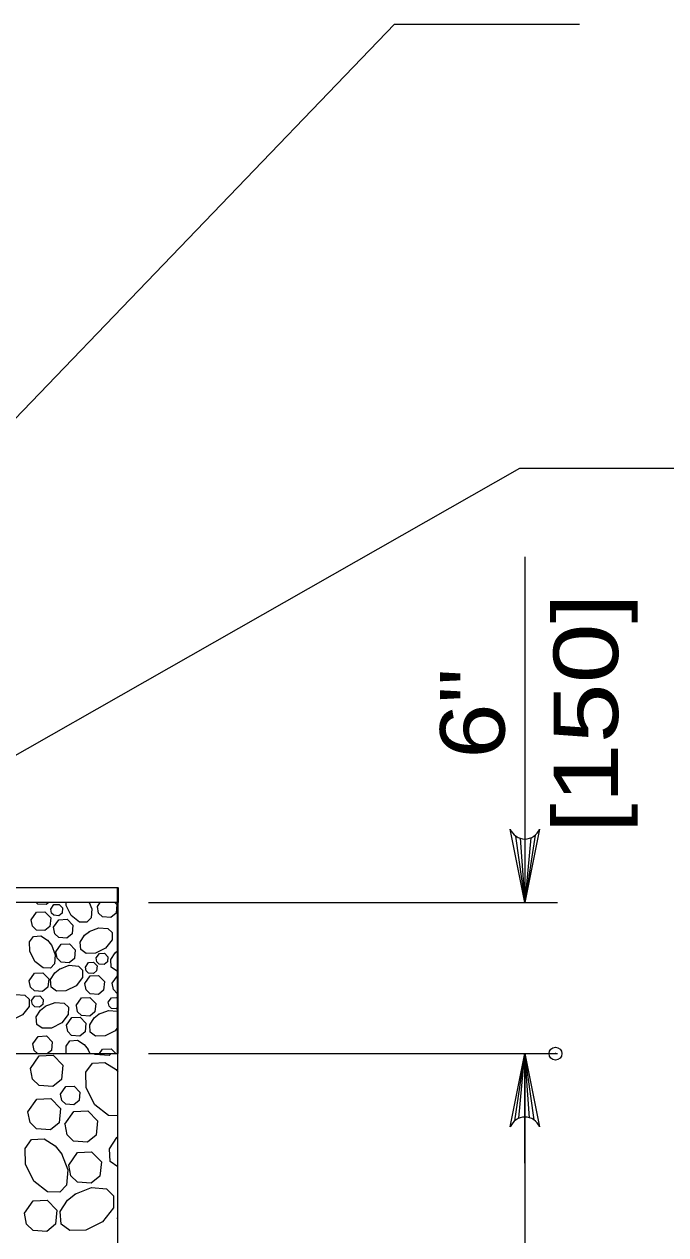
# Model space of a CAD drawing. Extents: x 1083.1 to 1117.1, y 697.4 to 741.4.
# Drawn here: x 1100.973 to 1102.523, y 705.8 to 708.723 of the extents above; entities that cross this region are included whole.
import ezdxf
from ezdxf.enums import TextEntityAlignment as Align

# ---------------------------------------------------------------- set-up
doc = ezdxf.new("R2010")
doc.units = 0
doc.header["$LTSCALE"] = 0.062
doc.header["$PDMODE"] = 32
doc.header["$PDSIZE"] = 0.031
doc.layers.add('1', color=7, linetype='Continuous', lineweight=13)

msp = doc.modelspace()

# ---------------------------------------------------------------- linework, layer by layer
at = {"layer": '1'}
for p, q in [((1102.18242, 707.4375), (1102.18242, 706.60292)), ((1102.16, 706.76317), (1102.18242, 706.60292)), ((1102.17108, 706.75767), (1102.18242, 706.60292)), ((1102.20725, 706.765), (1102.18242, 706.60292)), ((1102.19683, 706.75892), (1102.18242, 706.60292)), ((1102.18242, 706.75608), (1102.18242, 706.60292)), ((1101.14967, 706.593), (1101.15667, 706.60292)), ((1101.27317, 706.60292), (1102.26108, 706.60292)), ((1101.12683, 706.24842), (1101.13108, 706.23775)), ((1101.27317, 706.23775), (1102.26108, 706.23775)), ((1102.15767, 706.07558), (1102.18242, 706.23775)), ((1102.16808, 706.08175), (1102.18242, 706.23775)), ((1102.18242, 706.23775), (1102.18242, 704.29175)), ((1102.18242, 705.97342), (1102.18242, 706.23775)), ((1102.18242, 706.08458), (1102.18242, 706.23775)), ((1102.19375, 706.08292), (1102.18242, 706.23775)), ((1102.20483, 706.0775), (1102.18242, 706.23775)), ((1101.19808, 705.841), (1101.19942, 705.84283)), ((1101.19942, 705.8345), (1101.19808, 705.84092))]:
    msp.add_line(p, q, dxfattribs=at)
at = {"layer": '1', "lineweight": 25}
for p, q in [((1101.19942, 706.63767), (1098.91383, 706.63767)), ((1098.91383, 706.23775), (1101.19942, 706.23775))]:
    msp.add_line(p, q, dxfattribs=at)
at = {"layer": '1'}
for points in [[(1099.87325, 706.64992), (1101.86758, 708.7235), (1102.3145, 708.7235)], [(1100.01742, 706.42642), (1102.17033, 707.65183), (1102.60283, 707.65183)], [(1102.21783, 706.77992), (1102.18242, 706.60292), (1102.14708, 706.77992)], [(1101.03267, 706.60292), (1101.02608, 706.59742), (1101.00608, 706.59883), (1101.00183, 706.60292)], [(1101.13008, 706.60292), (1101.13625, 706.58717), (1101.13442, 706.56533), (1101.1245, 706.555), (1101.10675, 706.55525), (1101.08675, 706.571), (1101.0745, 706.59533), (1101.07442, 706.60292)], [(1101.19158, 706.60292), (1101.19675, 706.5975), (1101.19467, 706.57708), (1101.18217, 706.56667), (1101.16208, 706.56808), (1101.15275, 706.57725), (1101.14967, 706.593)], [(1101.0385, 706.50033), (1101.04792, 706.47658), (1101.04608, 706.45475), (1101.03625, 706.44433), (1101.0185, 706.44475), (1100.99842, 706.4605), (1100.98625, 706.48483), (1100.98592, 706.50767), (1100.995, 706.52058), (1101.01325, 706.52183), (1101.02958, 706.51133), (1101.03917, 706.49933)], [(1101.12967, 706.53242), (1101.15333, 706.54183), (1101.17525, 706.53992), (1101.1855, 706.53008), (1101.18525, 706.51242), (1101.1695, 706.49225), (1101.14517, 706.48017), (1101.12225, 706.47967), (1101.10942, 706.48892), (1101.10817, 706.50717), (1101.11858, 706.52342), (1101.13067, 706.533)], [(1101.19942, 706.43733), (1101.19592, 706.43725), (1101.183, 706.4465), (1101.18183, 706.46475), (1101.19233, 706.481), (1101.19942, 706.48667)], [(1101.05817, 706.44158), (1101.08192, 706.45108), (1101.10375, 706.44917), (1101.11408, 706.43933), (1101.11375, 706.42167), (1101.09808, 706.4015), (1101.07375, 706.38933), (1101.05083, 706.38892), (1101.03792, 706.39808), (1101.03667, 706.41633), (1101.04717, 706.43267), (1101.05917, 706.44225)], [(1101.18517, 706.40783), (1101.19792, 706.42592), (1101.19942, 706.426)], [(1101.19942, 706.38283), (1101.19767, 706.383), (1101.18825, 706.39217), (1101.18525, 706.40783)], [(1100.92908, 706.37142), (1100.95283, 706.38083), (1100.97467, 706.37892), (1100.985, 706.36908), (1100.98467, 706.35142), (1100.969, 706.33125), (1100.94467, 706.31917), (1100.92167, 706.31875), (1100.90875, 706.32783), (1100.90758, 706.34608), (1100.91808, 706.3625), (1100.93, 706.372)], [(1100.99075, 706.36583), (1100.99842, 706.37667), (1101.01058, 706.37733), (1101.019, 706.36858), (1101.01783, 706.35633), (1101.01025, 706.35008), (1100.99833, 706.35092), (1100.99267, 706.35642), (1100.99083, 706.36583)], [(1101.02375, 706.35192), (1101.04742, 706.36133), (1101.06925, 706.3595), (1101.07958, 706.34958), (1101.07925, 706.33192), (1101.0635, 706.31183), (1101.03925, 706.29958), (1101.01633, 706.29925), (1101.00342, 706.30833), (1101.00217, 706.32658), (1101.01267, 706.343), (1101.02467, 706.35258)], [(1101.09883, 706.35425), (1101.11158, 706.37233), (1101.13183, 706.3735), (1101.146, 706.35883), (1101.14392, 706.33842), (1101.13133, 706.32792), (1101.11133, 706.32942), (1101.10192, 706.33858), (1101.09892, 706.35425)], [(1101.17583, 706.36167), (1101.1835, 706.3725), (1101.19567, 706.37317), (1101.19942, 706.36933)], [(1101.19942, 706.34925), (1101.19533, 706.34592), (1101.18342, 706.34675), (1101.17775, 706.35225), (1101.17592, 706.36167)], [(1101.19942, 706.30133), (1101.1925, 706.29267), (1101.16825, 706.28042), (1101.14533, 706.28), (1101.13242, 706.28917), (1101.13117, 706.30742), (1101.14167, 706.32375), (1101.15367, 706.33342)], [(1101.15267, 706.33275), (1101.17642, 706.34208), (1101.19817, 706.34025), (1101.19942, 706.33908)], [(1100.99358, 706.26117), (1101.00633, 706.27925), (1101.02658, 706.28033), (1101.04067, 706.26583), (1101.03858, 706.24533), (1101.0295, 706.23775)], [(1101.00467, 706.23775), (1100.99667, 706.2455), (1100.99358, 706.26117)], [(1101.07442, 706.23775), (1101.07417, 706.25583), (1101.08333, 706.26875), (1101.10158, 706.26992), (1101.11792, 706.25942), (1101.1275, 706.2475)], [(1100.98792, 706.20183), (1101.00908, 706.232), (1101.04292, 706.23383), (1101.06633, 706.20958), (1101.063, 706.17542), (1101.04217, 706.15808), (1101.00875, 706.1605), (1100.993, 706.17575), (1100.988, 706.20183)], [(1101.18275, 706.23775), (1101.17775, 706.23358), (1101.14442, 706.236), (1101.14258, 706.23775)], [(1101.15475, 706.23775), (1101.16233, 706.2485), (1101.18258, 706.24967), (1101.19408, 706.23775)], [(1102.14708, 706.06075), (1102.18242, 706.23775), (1102.21783, 706.06075)], [(1101.19942, 706.08758), (1101.17667, 706.08792), (1101.14317, 706.11425), (1101.12283, 706.15475), (1101.12217, 706.19292), (1101.1375, 706.21442), (1101.16792, 706.21642), (1101.19517, 706.199), (1101.19942, 706.19367)], [(1101.06058, 706.14017), (1101.07333, 706.15825), (1101.09358, 706.15942), (1101.10767, 706.14483), (1101.10567, 706.12433), (1101.09308, 706.11392), (1101.07308, 706.11542), (1101.06367, 706.1245), (1101.06067, 706.14017)], [(1101.07142, 706.0675), (1101.09258, 706.09758), (1101.12633, 706.0995), (1101.14983, 706.07517), (1101.14642, 706.04108), (1101.12558, 706.02367), (1101.09225, 706.02608), (1101.0765, 706.04133), (1101.0715, 706.0675)], [(1101.06283, 705.99633), (1101.07858, 705.95683), (1101.07542, 705.92042), (1101.059, 705.90317), (1101.0295, 705.90367), (1100.99592, 705.92992), (1100.97575, 705.97042), (1100.975, 706.00867), (1100.99025, 706.03008), (1101.02075, 706.03217), (1101.04792, 706.01467), (1101.06383, 705.99475)], [(1101.19942, 705.96408), (1101.18092, 705.97725), (1101.17883, 706.00767), (1101.19633, 706.03492), (1101.19942, 706.03733)], [(1101.09558, 705.8985), (1101.13517, 705.91425), (1101.1715, 705.91108), (1101.18883, 705.89467), (1101.18825, 705.86517), (1101.162, 705.83167), (1101.1215, 705.81133), (1101.08333, 705.81075), (1101.06183, 705.826), (1101.05983, 705.85642), (1101.07717, 705.88358), (1101.09717, 705.8995)], [(1100.97358, 705.85208), (1100.99475, 705.88225), (1101.02858, 705.88408), (1101.052, 705.85983), (1101.04867, 705.82567), (1101.02783, 705.80833), (1100.99442, 705.81075), (1100.97875, 705.826), (1100.97367, 705.85208)]]:
    msp.add_lwpolyline(points, dxfattribs=at)
at = {"layer": '1', "lineweight": 25}
for points in [[(1101.19942, 706.23775), (1101.19942, 706.63767), (1101.19942, 706.60292), (1098.91383, 706.60292)], [(1100.04408, 704.29175), (1101.19942, 704.29175), (1101.19942, 706.63767)], [(1101.19942, 706.23775), (1101.19942, 706.63767), (1101.19942, 706.60292)]]:
    msp.add_lwpolyline(points, dxfattribs=at)
at = {"layer": '1', "lineweight": 35}
msp.add_lwpolyline([(1101.19942, 706.23775), (1101.19942, 706.63767), (1101.19942, 706.60292)], dxfattribs=at)
at = {"layer": '1'}
for points in [[(1100.99008, 706.561), (1101.00275, 706.579), (1101.023, 706.58017), (1101.03708, 706.56558), (1101.03508, 706.54508), (1101.0225, 706.53467), (1101.00258, 706.53608), (1100.99308, 706.54525)], [(1101.03725, 706.58667), (1101.04483, 706.5975), (1101.057, 706.59817), (1101.06542, 706.58942), (1101.06425, 706.57717), (1101.05667, 706.57083), (1101.04475, 706.57175), (1101.03908, 706.57725)], [(1101.04367, 706.543), (1101.05633, 706.56108), (1101.07667, 706.56225), (1101.09075, 706.54767), (1101.08867, 706.52717), (1101.07617, 706.51675), (1101.05617, 706.51817), (1101.04675, 706.52733)], [(1101.04933, 706.48367), (1101.062, 706.50167), (1101.08233, 706.50283), (1101.09642, 706.48817), (1101.09433, 706.46775), (1101.08183, 706.45733), (1101.06183, 706.45875), (1101.05242, 706.46792)], [(1101.14675, 706.46883), (1101.15442, 706.47958), (1101.1665, 706.48033), (1101.175, 706.47158), (1101.17375, 706.45933), (1101.16625, 706.453), (1101.15425, 706.45392), (1101.14858, 706.45942)], [(1100.985, 706.41375), (1100.99767, 706.43183), (1101.018, 706.43308), (1101.03208, 706.41842), (1101.03, 706.39792), (1101.0175, 706.3875), (1100.9975, 706.389), (1100.98808, 706.39808)], [(1101.12058, 706.44683), (1101.12817, 706.45758), (1101.14033, 706.45833), (1101.14883, 706.44958), (1101.14758, 706.43725), (1101.14008, 706.431), (1101.128, 706.43183), (1101.12233, 706.43733)], [(1101.11967, 706.40708), (1101.13233, 706.42517), (1101.15267, 706.42633), (1101.16675, 706.41175), (1101.16467, 706.39125), (1101.15217, 706.38083), (1101.13217, 706.38233), (1101.12275, 706.39142)], [(1101.075, 706.3065), (1101.08767, 706.32458), (1101.108, 706.32567), (1101.12208, 706.31108), (1101.12, 706.29058), (1101.1075, 706.28017), (1101.08742, 706.28167), (1101.07808, 706.29083)], [(1100.982, 706.09742), (1101.00317, 706.12742), (1101.03692, 706.12942), (1101.06042, 706.10508), (1101.05708, 706.07092), (1101.03617, 706.05358), (1101.00283, 706.056), (1100.98717, 706.07117)], [(1101.08083, 705.9685), (1101.102, 705.99858), (1101.13575, 706.0005), (1101.15925, 705.97617), (1101.15583, 705.94208), (1101.13492, 705.92467), (1101.10158, 705.92717), (1101.08592, 705.94233)]]:
    msp.add_lwpolyline(points, close=True, dxfattribs=at)
for centre, start, end in [((1102.1824, 706.79418), 202.08782, 337.91395), ((1102.18248, 706.04642), 22.08782, 157.91395)]:
    msp.add_arc(centre, 0.0382, start, end, dxfattribs=at)
msp.add_point((1102.25625, 706.23775), dxfattribs=at)

# ---------------------------------------------------------------- texts
for s, width, p in [('[150]', 1.25, (1102.4075, 707.05925)), ('6"', 1.15, (1102.1335, 707.05925))]:
    msp.add_text(s, height=0.156, rotation=90, dxfattribs=dict(at, width=width)).set_placement(p, align=Align.CENTER)

doc.saveas('drawing.dxf')
